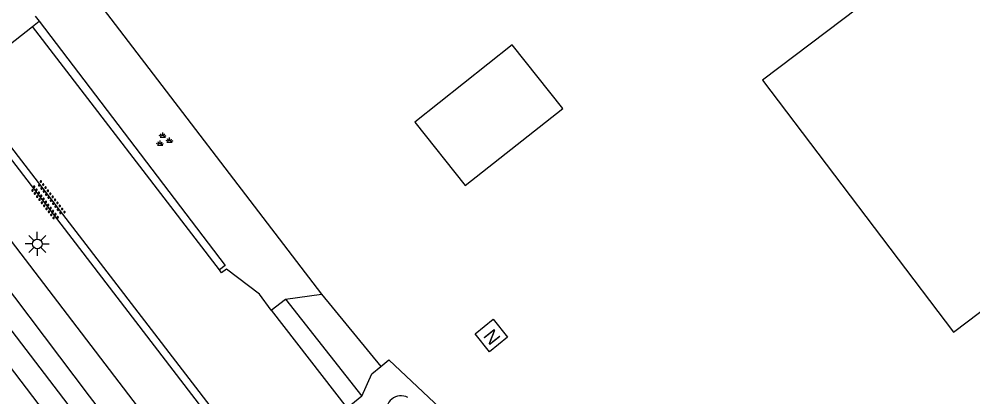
# Model space of a CAD drawing. Extents: x 136000 to 141000, y 400494 to 402006.
# Drawn here: x 136401.45 to 136450.96, y 401617.61 to 401637.23 of the extents above; entities that cross this region are included whole.
import ezdxf

# ---------------------------------------------------------------- set-up
doc = ezdxf.new("R2010")
doc.units = 0
for name, color, linetype in [('gg-afsc-erfafscheiding', 7, 'Continuous'), ('gg-bbg-bijgebouw', 7, 'Continuous'), ('gg-knt-verharding', 7, 'Continuous'), ('gg-kntw-bovenkant insteek waterloop', 7, 'Continuous'), ('gg-kntw-waterlijn', 7, 'Continuous'), ('gt-grn-groengrens', 7, 'Continuous'), ('gt-grn-weggrens', 7, 'Continuous'), ('gt-symb-groenvak', 7, 'Continuous'), ('gt-symb-lichtmast', 7, 'Continuous'), ('gt-symb-nortonput', 7, 'Continuous'), ('gt-symb-overige verharding', 7, 'Continuous')]:
    doc.layers.add(name, color=color, linetype=linetype)

# ---------------------------------------------------------------- blocks, each defined once
blk = doc.blocks.new('gt0-NPUT')
at = {"layer": 'gt-symb-nortonput'}
blk.add_lwpolyline([(-0.566, -0.608), (-0.566, 0.592), (0.634, 0.592), (0.634, -0.608)], close=True, dxfattribs=at)
blk.add_text('N', height=0.7, dxfattribs=at).set_placement((-0.221, -0.381))
blk = doc.blocks.new('gt0-GRVAK')
at = {"layer": 'gt-symb-groenvak'}
for p, q in [((-0.11, 0.189), (-0.228, 0.24)), ((-0.182, 0.153), (0.088, 0.153)), ((-0.091, 0.211), (-0.156, 0.322)), ((-0.047, 0.214), (-0.047, 0.393)), ((-0.004, 0.211), (0.061, 0.322)), ((0.015, 0.189), (0.133, 0.24)), ((0.262, -0.052), (0.197, 0.059)), ((0.305, -0.049), (0.305, 0.13)), ((0.349, -0.052), (0.414, 0.059)), ((-0.245, -0.228), (-0.363, -0.177)), ((-0.318, -0.264), (-0.047, -0.264)), ((-0.226, -0.206), (-0.291, -0.095)), ((-0.183, -0.203), (-0.183, -0.024)), ((-0.139, -0.206), (-0.074, -0.095)), ((-0.12, -0.228), (-0.002, -0.177)), ((0.243, -0.074), (0.125, -0.023)), ((0.17, -0.11), (0.441, -0.11)), ((0.368, -0.074), (0.486, -0.023))]:
    blk.add_line(p, q, dxfattribs=at)
blk = doc.blocks.new('gt0-LMAST')
at = {"layer": 'gt-symb-lichtmast'}
for p, q in [((-0.005, 0.246), (-0.005, 0.621)), ((-0.182, 0.173), (-0.447, 0.438)), ((0.172, 0.173), (0.437, 0.438)), ((-0.255, -0.004), (-0.63, -0.004)), ((-0.182, -0.181), (-0.447, -0.446)), ((-0.005, -0.254), (-0.005, -0.629)), ((0.437, -0.446), (0.172, -0.181)), ((0.245, -0.004), (0.62, -0.004))]:
    blk.add_line(p, q, dxfattribs=at)
blk.add_circle((-0.005, -0.004), 0.25, dxfattribs=at)
blk = doc.blocks.new('gt0-OVH')
at = {"layer": 'gt-symb-overige verharding'}
for points in [[(-0.972, 0.298), (-0.967, 0.308), (-0.965, 0.319), (-0.966, 0.33), (-0.971, 0.34), (-0.978, 0.348), (-0.988, 0.353), (-0.999, 0.355), (-1.01, 0.354), (-1.02, 0.349), (-1.028, 0.342), (-1.033, 0.332), (-1.035, 0.321), (-1.034, 0.31), (-1.029, 0.3), (-1.022, 0.292), (-1.012, 0.287), (-1.001, 0.285), (-0.99, 0.286), (-0.98, 0.291)], [(-0.872, 0.106), (-0.867, 0.116), (-0.865, 0.126), (-0.866, 0.137), (-0.871, 0.147), (-0.878, 0.156), (-0.888, 0.161), (-0.899, 0.163), (-0.91, 0.162), (-0.92, 0.157), (-0.928, 0.15), (-0.933, 0.14), (-0.935, 0.129), (-0.934, 0.118), (-0.929, 0.108), (-0.922, 0.1), (-0.912, 0.095), (-0.901, 0.092), (-0.89, 0.094), (-0.88, 0.098)], [(-0.772, 0.298), (-0.767, 0.308), (-0.765, 0.319), (-0.766, 0.33), (-0.771, 0.34), (-0.778, 0.348), (-0.788, 0.353), (-0.799, 0.355), (-0.81, 0.354), (-0.82, 0.349), (-0.828, 0.342), (-0.833, 0.332), (-0.835, 0.321), (-0.834, 0.31), (-0.829, 0.3), (-0.822, 0.292), (-0.812, 0.287), (-0.801, 0.285), (-0.79, 0.286), (-0.78, 0.291)], [(-0.672, 0.106), (-0.667, 0.116), (-0.665, 0.126), (-0.666, 0.137), (-0.671, 0.147), (-0.678, 0.156), (-0.688, 0.161), (-0.699, 0.163), (-0.71, 0.162), (-0.72, 0.157), (-0.728, 0.15), (-0.733, 0.14), (-0.735, 0.129), (-0.734, 0.118), (-0.729, 0.108), (-0.722, 0.1), (-0.712, 0.095), (-0.701, 0.092), (-0.69, 0.094), (-0.68, 0.098)], [(-0.572, 0.298), (-0.567, 0.308), (-0.565, 0.319), (-0.566, 0.33), (-0.571, 0.34), (-0.578, 0.348), (-0.588, 0.353), (-0.599, 0.355), (-0.61, 0.354), (-0.62, 0.349), (-0.628, 0.342), (-0.633, 0.332), (-0.635, 0.321), (-0.634, 0.31), (-0.629, 0.3), (-0.622, 0.292), (-0.612, 0.287), (-0.601, 0.285), (-0.59, 0.286), (-0.58, 0.291)], [(-0.472, 0.106), (-0.467, 0.116), (-0.465, 0.126), (-0.466, 0.137), (-0.471, 0.147), (-0.478, 0.156), (-0.488, 0.161), (-0.499, 0.163), (-0.51, 0.162), (-0.52, 0.157), (-0.528, 0.15), (-0.533, 0.14), (-0.535, 0.129), (-0.534, 0.118), (-0.529, 0.108), (-0.522, 0.1), (-0.512, 0.095), (-0.501, 0.092), (-0.49, 0.094), (-0.48, 0.098)], [(-0.372, 0.298), (-0.367, 0.308), (-0.365, 0.319), (-0.366, 0.33), (-0.371, 0.34), (-0.378, 0.348), (-0.388, 0.353), (-0.399, 0.355), (-0.41, 0.354), (-0.42, 0.349), (-0.428, 0.342), (-0.433, 0.332), (-0.435, 0.321), (-0.434, 0.31), (-0.429, 0.3), (-0.422, 0.292), (-0.412, 0.287), (-0.401, 0.285), (-0.39, 0.286), (-0.38, 0.291)], [(-0.272, 0.106), (-0.267, 0.116), (-0.265, 0.126), (-0.266, 0.137), (-0.271, 0.147), (-0.278, 0.156), (-0.288, 0.161), (-0.299, 0.163), (-0.31, 0.162), (-0.32, 0.157), (-0.328, 0.15), (-0.333, 0.14), (-0.335, 0.129), (-0.334, 0.118), (-0.329, 0.108), (-0.322, 0.1), (-0.312, 0.095), (-0.301, 0.092), (-0.29, 0.094), (-0.28, 0.098)], [(-0.172, 0.298), (-0.167, 0.308), (-0.165, 0.319), (-0.166, 0.33), (-0.171, 0.34), (-0.178, 0.348), (-0.188, 0.353), (-0.199, 0.355), (-0.21, 0.354), (-0.22, 0.349), (-0.228, 0.342), (-0.233, 0.332), (-0.235, 0.321), (-0.234, 0.31), (-0.229, 0.3), (-0.222, 0.292), (-0.212, 0.287), (-0.201, 0.285), (-0.19, 0.286), (-0.18, 0.291)], [(-0.072, 0.106), (-0.067, 0.116), (-0.065, 0.126), (-0.066, 0.137), (-0.071, 0.147), (-0.078, 0.156), (-0.088, 0.161), (-0.099, 0.163), (-0.11, 0.162), (-0.12, 0.157), (-0.128, 0.15), (-0.133, 0.14), (-0.135, 0.129), (-0.134, 0.118), (-0.129, 0.108), (-0.122, 0.1), (-0.112, 0.095), (-0.101, 0.092), (-0.09, 0.094), (-0.08, 0.098)], [(0.028, 0.298), (0.033, 0.308), (0.035, 0.319), (0.034, 0.33), (0.029, 0.34), (0.022, 0.348), (0.012, 0.353), (0.001, 0.355), (-0.01, 0.354), (-0.02, 0.349), (-0.028, 0.342), (-0.033, 0.332), (-0.035, 0.321), (-0.034, 0.31), (-0.029, 0.3), (-0.022, 0.292), (-0.012, 0.287), (-0.001, 0.285), (0.01, 0.286), (0.02, 0.291)], [(0.128, 0.106), (0.133, 0.116), (0.135, 0.126), (0.134, 0.137), (0.129, 0.147), (0.122, 0.156), (0.112, 0.161), (0.101, 0.163), (0.09, 0.162), (0.08, 0.157), (0.072, 0.15), (0.067, 0.14), (0.065, 0.129), (0.066, 0.118), (0.071, 0.108), (0.078, 0.1), (0.088, 0.095), (0.099, 0.092), (0.11, 0.094), (0.12, 0.098)], [(0.228, 0.298), (0.233, 0.308), (0.235, 0.319), (0.234, 0.33), (0.229, 0.34), (0.222, 0.348), (0.212, 0.353), (0.201, 0.355), (0.19, 0.354), (0.18, 0.349), (0.172, 0.342), (0.167, 0.332), (0.165, 0.321), (0.166, 0.31), (0.171, 0.3), (0.178, 0.292), (0.188, 0.287), (0.199, 0.285), (0.21, 0.286), (0.22, 0.291)], [(0.328, 0.106), (0.333, 0.116), (0.335, 0.126), (0.334, 0.137), (0.329, 0.147), (0.322, 0.156), (0.312, 0.161), (0.301, 0.163), (0.29, 0.162), (0.28, 0.157), (0.272, 0.15), (0.267, 0.14), (0.265, 0.129), (0.266, 0.118), (0.271, 0.108), (0.278, 0.1), (0.288, 0.095), (0.299, 0.092), (0.31, 0.094), (0.32, 0.098)], [(0.428, 0.298), (0.433, 0.308), (0.435, 0.319), (0.434, 0.33), (0.429, 0.34), (0.422, 0.348), (0.412, 0.353), (0.401, 0.355), (0.39, 0.354), (0.38, 0.349), (0.372, 0.342), (0.367, 0.332), (0.365, 0.321), (0.366, 0.31), (0.371, 0.3), (0.378, 0.292), (0.388, 0.287), (0.399, 0.285), (0.41, 0.286), (0.42, 0.291)], [(0.528, 0.106), (0.533, 0.116), (0.535, 0.126), (0.534, 0.137), (0.529, 0.147), (0.522, 0.156), (0.512, 0.161), (0.501, 0.163), (0.49, 0.162), (0.48, 0.157), (0.472, 0.15), (0.467, 0.14), (0.465, 0.129), (0.466, 0.118), (0.471, 0.108), (0.478, 0.1), (0.488, 0.095), (0.499, 0.092), (0.51, 0.094), (0.52, 0.098)], [(0.628, 0.298), (0.633, 0.308), (0.635, 0.319), (0.634, 0.33), (0.629, 0.34), (0.622, 0.348), (0.612, 0.353), (0.601, 0.355), (0.59, 0.354), (0.58, 0.349), (0.572, 0.342), (0.567, 0.332), (0.565, 0.321), (0.566, 0.31), (0.571, 0.3), (0.578, 0.292), (0.588, 0.287), (0.599, 0.285), (0.61, 0.286), (0.62, 0.291)], [(0.728, 0.106), (0.733, 0.116), (0.735, 0.126), (0.734, 0.137), (0.729, 0.147), (0.722, 0.156), (0.712, 0.161), (0.701, 0.163), (0.69, 0.162), (0.68, 0.157), (0.672, 0.15), (0.667, 0.14), (0.665, 0.129), (0.666, 0.118), (0.671, 0.108), (0.678, 0.1), (0.688, 0.095), (0.699, 0.092), (0.71, 0.094), (0.72, 0.098)], [(0.828, 0.298), (0.833, 0.308), (0.835, 0.319), (0.834, 0.33), (0.829, 0.34), (0.822, 0.348), (0.812, 0.353), (0.801, 0.355), (0.79, 0.354), (0.78, 0.349), (0.772, 0.342), (0.767, 0.332), (0.765, 0.321), (0.766, 0.31), (0.771, 0.3), (0.778, 0.292), (0.788, 0.287), (0.799, 0.285), (0.81, 0.286), (0.82, 0.291)], [(0.928, 0.106), (0.933, 0.116), (0.935, 0.126), (0.934, 0.137), (0.929, 0.147), (0.922, 0.156), (0.912, 0.161), (0.901, 0.163), (0.89, 0.162), (0.88, 0.157), (0.872, 0.15), (0.867, 0.14), (0.865, 0.129), (0.866, 0.118), (0.871, 0.108), (0.878, 0.1), (0.888, 0.095), (0.899, 0.092), (0.91, 0.094), (0.92, 0.098)], [(1.028, 0.298), (1.033, 0.308), (1.035, 0.319), (1.034, 0.33), (1.029, 0.34), (1.022, 0.348), (1.012, 0.353), (1.001, 0.355), (0.99, 0.354), (0.98, 0.349), (0.972, 0.342), (0.967, 0.332), (0.965, 0.321), (0.966, 0.31), (0.971, 0.3), (0.978, 0.292), (0.988, 0.287), (0.999, 0.285), (1.01, 0.286), (1.02, 0.291)], [(-0.972, -0.142), (-0.967, -0.132), (-0.965, -0.121), (-0.966, -0.11), (-0.971, -0.1), (-0.978, -0.092), (-0.988, -0.087), (-0.999, -0.085), (-1.01, -0.086), (-1.02, -0.091), (-1.028, -0.098), (-1.033, -0.108), (-1.035, -0.119), (-1.034, -0.13), (-1.029, -0.14), (-1.022, -0.148), (-1.012, -0.153), (-1.001, -0.155), (-0.99, -0.154), (-0.98, -0.149)], [(-0.872, -0.334), (-0.867, -0.324), (-0.865, -0.314), (-0.866, -0.303), (-0.871, -0.293), (-0.878, -0.284), (-0.888, -0.279), (-0.899, -0.277), (-0.91, -0.278), (-0.92, -0.283), (-0.928, -0.29), (-0.933, -0.3), (-0.935, -0.311), (-0.934, -0.322), (-0.929, -0.332), (-0.922, -0.34), (-0.912, -0.345), (-0.901, -0.348), (-0.89, -0.346), (-0.88, -0.342)], [(-0.772, -0.142), (-0.767, -0.132), (-0.765, -0.121), (-0.766, -0.11), (-0.771, -0.1), (-0.778, -0.092), (-0.788, -0.087), (-0.799, -0.085), (-0.81, -0.086), (-0.82, -0.091), (-0.828, -0.098), (-0.833, -0.108), (-0.835, -0.119), (-0.834, -0.13), (-0.829, -0.14), (-0.822, -0.148), (-0.812, -0.153), (-0.801, -0.155), (-0.79, -0.154), (-0.78, -0.149)], [(-0.672, -0.334), (-0.667, -0.324), (-0.665, -0.314), (-0.666, -0.303), (-0.671, -0.293), (-0.678, -0.284), (-0.688, -0.279), (-0.699, -0.277), (-0.71, -0.278), (-0.72, -0.283), (-0.728, -0.29), (-0.733, -0.3), (-0.735, -0.311), (-0.734, -0.322), (-0.729, -0.332), (-0.722, -0.34), (-0.712, -0.345), (-0.701, -0.348), (-0.69, -0.346), (-0.68, -0.342)], [(-0.572, -0.142), (-0.567, -0.132), (-0.565, -0.121), (-0.566, -0.11), (-0.571, -0.1), (-0.578, -0.092), (-0.588, -0.087), (-0.599, -0.085), (-0.61, -0.086), (-0.62, -0.091), (-0.628, -0.098), (-0.633, -0.108), (-0.635, -0.119), (-0.634, -0.13), (-0.629, -0.14), (-0.622, -0.148), (-0.612, -0.153), (-0.601, -0.155), (-0.59, -0.154), (-0.58, -0.149)], [(-0.472, -0.334), (-0.467, -0.324), (-0.465, -0.314), (-0.466, -0.303), (-0.471, -0.293), (-0.478, -0.284), (-0.488, -0.279), (-0.499, -0.277), (-0.51, -0.278), (-0.52, -0.283), (-0.528, -0.29), (-0.533, -0.3), (-0.535, -0.311), (-0.534, -0.322), (-0.529, -0.332), (-0.522, -0.34), (-0.512, -0.345), (-0.501, -0.348), (-0.49, -0.346), (-0.48, -0.342)], [(-0.372, -0.142), (-0.367, -0.132), (-0.365, -0.121), (-0.366, -0.11), (-0.371, -0.1), (-0.378, -0.092), (-0.388, -0.087), (-0.399, -0.085), (-0.41, -0.086), (-0.42, -0.091), (-0.428, -0.098), (-0.433, -0.108), (-0.435, -0.119), (-0.434, -0.13), (-0.429, -0.14), (-0.422, -0.148), (-0.412, -0.153), (-0.401, -0.155), (-0.39, -0.154), (-0.38, -0.149)], [(-0.272, -0.334), (-0.267, -0.324), (-0.265, -0.314), (-0.266, -0.303), (-0.271, -0.293), (-0.278, -0.284), (-0.288, -0.279), (-0.299, -0.277), (-0.31, -0.278), (-0.32, -0.283), (-0.328, -0.29), (-0.333, -0.3), (-0.335, -0.311), (-0.334, -0.322), (-0.329, -0.332), (-0.322, -0.34), (-0.312, -0.345), (-0.301, -0.348), (-0.29, -0.346), (-0.28, -0.342)], [(-0.172, -0.142), (-0.167, -0.132), (-0.165, -0.121), (-0.166, -0.11), (-0.171, -0.1), (-0.178, -0.092), (-0.188, -0.087), (-0.199, -0.085), (-0.21, -0.086), (-0.22, -0.091), (-0.228, -0.098), (-0.233, -0.108), (-0.235, -0.119), (-0.234, -0.13), (-0.229, -0.14), (-0.222, -0.148), (-0.212, -0.153), (-0.201, -0.155), (-0.19, -0.154), (-0.18, -0.149)], [(-0.072, -0.334), (-0.067, -0.324), (-0.065, -0.314), (-0.066, -0.303), (-0.071, -0.293), (-0.078, -0.284), (-0.088, -0.279), (-0.099, -0.277), (-0.11, -0.278), (-0.12, -0.283), (-0.128, -0.29), (-0.133, -0.3), (-0.135, -0.311), (-0.134, -0.322), (-0.129, -0.332), (-0.122, -0.34), (-0.112, -0.345), (-0.101, -0.348), (-0.09, -0.346), (-0.08, -0.342)], [(0.028, -0.142), (0.033, -0.132), (0.035, -0.121), (0.034, -0.11), (0.029, -0.1), (0.022, -0.092), (0.012, -0.087), (0.001, -0.085), (-0.01, -0.086), (-0.02, -0.091), (-0.028, -0.098), (-0.033, -0.108), (-0.035, -0.119), (-0.034, -0.13), (-0.029, -0.14), (-0.022, -0.148), (-0.012, -0.153), (-0.001, -0.155), (0.01, -0.154), (0.02, -0.149)], [(0.128, -0.334), (0.133, -0.324), (0.135, -0.314), (0.134, -0.303), (0.129, -0.293), (0.122, -0.284), (0.112, -0.279), (0.101, -0.277), (0.09, -0.278), (0.08, -0.283), (0.072, -0.29), (0.067, -0.3), (0.065, -0.311), (0.066, -0.322), (0.071, -0.332), (0.078, -0.34), (0.088, -0.345), (0.099, -0.348), (0.11, -0.346), (0.12, -0.342)], [(0.228, -0.142), (0.233, -0.132), (0.235, -0.121), (0.234, -0.11), (0.229, -0.1), (0.222, -0.092), (0.212, -0.087), (0.201, -0.085), (0.19, -0.086), (0.18, -0.091), (0.172, -0.098), (0.167, -0.108), (0.165, -0.119), (0.166, -0.13), (0.171, -0.14), (0.178, -0.148), (0.188, -0.153), (0.199, -0.155), (0.21, -0.154), (0.22, -0.149)], [(0.328, -0.334), (0.333, -0.324), (0.335, -0.314), (0.334, -0.303), (0.329, -0.293), (0.322, -0.284), (0.312, -0.279), (0.301, -0.277), (0.29, -0.278), (0.28, -0.283), (0.272, -0.29), (0.267, -0.3), (0.265, -0.311), (0.266, -0.322), (0.271, -0.332), (0.278, -0.34), (0.288, -0.345), (0.299, -0.348), (0.31, -0.346), (0.32, -0.342)], [(0.428, -0.142), (0.433, -0.132), (0.435, -0.121), (0.434, -0.11), (0.429, -0.1), (0.422, -0.092), (0.412, -0.087), (0.401, -0.085), (0.39, -0.086), (0.38, -0.091), (0.372, -0.098), (0.367, -0.108), (0.365, -0.119), (0.366, -0.13), (0.371, -0.14), (0.378, -0.148), (0.388, -0.153), (0.399, -0.155), (0.41, -0.154), (0.42, -0.149)], [(0.528, -0.334), (0.533, -0.324), (0.535, -0.314), (0.534, -0.303), (0.529, -0.293), (0.522, -0.284), (0.512, -0.279), (0.501, -0.277), (0.49, -0.278), (0.48, -0.283), (0.472, -0.29), (0.467, -0.3), (0.465, -0.311), (0.466, -0.322), (0.471, -0.332), (0.478, -0.34), (0.488, -0.345), (0.499, -0.348), (0.51, -0.346), (0.52, -0.342)], [(0.628, -0.142), (0.633, -0.132), (0.635, -0.121), (0.634, -0.11), (0.629, -0.1), (0.622, -0.092), (0.612, -0.087), (0.601, -0.085), (0.59, -0.086), (0.58, -0.091), (0.572, -0.098), (0.567, -0.108), (0.565, -0.119), (0.566, -0.13), (0.571, -0.14), (0.578, -0.148), (0.588, -0.153), (0.599, -0.155), (0.61, -0.154), (0.62, -0.149)], [(0.728, -0.334), (0.733, -0.324), (0.735, -0.314), (0.734, -0.303), (0.729, -0.293), (0.722, -0.284), (0.712, -0.279), (0.701, -0.277), (0.69, -0.278), (0.68, -0.283), (0.672, -0.29), (0.667, -0.3), (0.665, -0.311), (0.666, -0.322), (0.671, -0.332), (0.678, -0.34), (0.688, -0.345), (0.699, -0.348), (0.71, -0.346), (0.72, -0.342)], [(0.828, -0.142), (0.833, -0.132), (0.835, -0.121), (0.834, -0.11), (0.829, -0.1), (0.822, -0.092), (0.812, -0.087), (0.801, -0.085), (0.79, -0.086), (0.78, -0.091), (0.772, -0.098), (0.767, -0.108), (0.765, -0.119), (0.766, -0.13), (0.771, -0.14), (0.778, -0.148), (0.788, -0.153), (0.799, -0.155), (0.81, -0.154), (0.82, -0.149)], [(0.928, -0.334), (0.933, -0.324), (0.935, -0.314), (0.934, -0.303), (0.929, -0.293), (0.922, -0.284), (0.912, -0.279), (0.901, -0.277), (0.89, -0.278), (0.88, -0.283), (0.872, -0.29), (0.867, -0.3), (0.865, -0.311), (0.866, -0.322), (0.871, -0.332), (0.878, -0.34), (0.888, -0.345), (0.899, -0.348), (0.91, -0.346), (0.92, -0.342)], [(1.028, -0.142), (1.033, -0.132), (1.035, -0.121), (1.034, -0.11), (1.029, -0.1), (1.022, -0.092), (1.012, -0.087), (1.001, -0.085), (0.99, -0.086), (0.98, -0.091), (0.972, -0.098), (0.967, -0.108), (0.965, -0.119), (0.966, -0.13), (0.971, -0.14), (0.978, -0.148), (0.988, -0.153), (0.999, -0.155), (1.01, -0.154), (1.02, -0.149)]]:
    blk.add_lwpolyline(points, close=True, dxfattribs=at)

msp = doc.modelspace()

# ---------------------------------------------------------------- linework, layer by layer
at = {"layer": 'gg-afsc-erfafscheiding'}
msp.add_line((136403.675, 401640.568), (136417.155, 401622.951), dxfattribs=at)
at = {"layer": 'gg-bbg-bijgebouw'}
for points in [[(136451.636, 401642.827), (136440.042, 401634.053), (136449.946, 401620.965), (136461.62, 401629.799), (136489.408, 401650.646), (136479.608, 401663.709), (136451.636, 401642.827)], [(136421.996, 401631.877), (136424.615, 401628.585), (136429.671, 401632.592), (136427.052, 401635.884), (136421.996, 401631.877)]]:
    msp.add_lwpolyline(points, dxfattribs=at)
at = {"layer": 'gg-knt-verharding'}
for p, q in [((136402.153, 401636.85), (136402.491, 401637.118)), ((136402.294, 401637.374), (136402.491, 401637.118)), ((136411.848, 401624.201), (136402.153, 401636.85)), ((136443.709, 401575.132), (136398.446, 401633.954)), ((136412.946, 401614.458), (136398.158, 401633.714)), ((136414.545, 401622.106), (136415.283, 401622.686)), ((136415.283, 401622.686), (136417.155, 401622.951)), ((136415.283, 401622.686), (136419.248, 401617.64)), ((136417.155, 401622.951), (136420.226, 401619.186)), ((136414.545, 401622.106), (136418.486, 401617.028)), ((136419.761, 401618.807), (136420.226, 401619.186)), ((136420.226, 401619.186), (136420.65, 401619.532)), ((136419.248, 401617.64), (136419.761, 401618.807)), ((136419.248, 401617.64), (136418.486, 401617.028))]:
    msp.add_line(p, q, dxfattribs=at)
for points in [[(136402.491, 401637.118), (136412.158, 401624.439), (136411.848, 401624.201)], [(136414.545, 401622.106), (136413.934, 401622.941), (136412.219, 401624.25), (136411.964, 401624.05), (136411.848, 401624.201)]]:
    msp.add_lwpolyline(points, dxfattribs=at)
at = {"layer": 'gg-kntw-bovenkant insteek waterloop'}
for p, q in [((136410.836, 401612.912), (136400.143, 401626.878)), ((136396.982, 401624.394), (136436.696, 401572.363))]:
    msp.add_line(p, q, dxfattribs=at)
msp.add_arc((136421.265, 401616.939), 0.731, 60.4427, 199.5538, dxfattribs=at)
at = {"layer": 'gg-kntw-waterlijn'}
msp.add_lwpolyline([(136397.921, 401625.132), (136403.981, 401617.216), (136438.033, 401572.73), (136439.112, 401573.556), (136435.538, 401577.749), (136419.098, 401599.447), (136405.105, 401617.655), (136398.881, 401625.886)], dxfattribs=at)
at = {"layer": 'gt-grn-groengrens'}
msp.add_line((136420.65, 401619.532), (136424.152, 401616.234), dxfattribs=at)
at = {"layer": 'gt-grn-weggrens'}
msp.add_line((136398.446, 401633.954), (136402.153, 401636.85), dxfattribs=at)

# ---------------------------------------------------------------- block references
at = {"layer": 'gt-symb-groenvak'}
msp.add_blockref('gt0-GRVAK', (136408.957, 401630.946), dxfattribs=at)
at = {"layer": 'gt-symb-lichtmast'}
msp.add_blockref('gt0-LMAST', (136402.403, 401625.556), dxfattribs=at)
at = {"layer": 'gt-symb-nortonput', "rotation": -51.41174435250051}
msp.add_blockref('gt0-NPUT', (136425.948, 401620.829), dxfattribs=at)
at = {"layer": 'gt-symb-overige verharding', "rotation": -52.39646300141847}
msp.add_blockref('gt0-OVH', (136402.943, 401627.804), dxfattribs=at)

doc.saveas('drawing.dxf')
